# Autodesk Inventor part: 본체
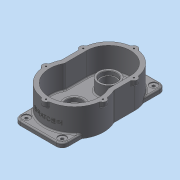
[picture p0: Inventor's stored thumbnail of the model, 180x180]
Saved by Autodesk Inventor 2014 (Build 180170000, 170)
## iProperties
Created: 2025-09
Part Number: 본체
Material: 일반
Document SubType Name: Modeling
Designer: dg
Density: 1 g/cm^3
Appearance: 기본값
Author: dg
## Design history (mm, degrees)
sketch "스케치1"
  geometry: L1 (-60, 0)-(-60, -48.184); L2 (60, 0)-(60, -48.184); A1 r 60 centre (0, 0) between (60, 0) and (-60, 0); A2 r 67 centre (0, -78) between (-60, -48.184) and (60, -48.184); 1 further point
  constraints: 4 end point, 4 point on circle, 2 centre point, 2 tangent, 1 coincident, 1 parallel, 1 vertical, 1 vertical alignment
  dimensions: "d0" = 120 diameter of A1; "d2" = 78 distance of point (0, 0) A2.centre; "d3" = 67 radius of A2
extrude "돌출1" new body sketch "스케치1" distance "d4" = 64; taper "d5" = 0 deg
feature "쉘1" dims "d6" = 10
sketch "스케치2"
  geometry: L1 (-55, 76)-(55, 76); L2 (55, 76)-(55, -161); L3 (55, -161)-(-55, -161); L4 (-55, -161)-(-55, 76); A1 r 60 centre (0, 0) between (60, 0) and (-60, 0) reference; 1 further point
  constraints: 8 end point, 2 parallel, 1 horizontal, 1 midpoint, 1 perpendicular, 1 vertical alignment
  dimensions: "d7" = 110 distance of L2.end L3.end; "d8" = 76 distance from line of L1 A1.centre; "d9" = 237 distance between parallel lines of L3 L1
extrude "돌출2" join sketch "스케치2" distance "d10" = 10; taper "d11" = 0 deg
sketch "스케치3"
  geometry: C1 r 23.5 at (0, 78); C2 r 23.5 at (0, 0); A1 r 57 centre (0, 0) between (-50, 27.368) and (50, 27.368) reference; A2 r 50 centre (0, 78) between (50, 78) and (-50, 78) reference
  constraints: 2 centre point, 2 coincident
  dimensions: "d12" = 47 diameter of C1; "d13" = 47 diameter of C2
extrude "돌출3" join sketch "스케치3" distance "d14" = 26; taper "d15" = 0 deg
extrude "돌출4" join sketch "스케치3" distance "d16" = 12; taper "d17" = 0 deg
hole "구멍1" diameter "d20" = 32; stored, may be unused: countersink angle "d24" = 90 deg, drill point angle "d26" = 0 deg; dims "d21" = 6, "d22" = 37, "d23" = 9, "d25" = 16, "d27" = 10, "d28" = 10
hole "구멍2" diameter "d31" = 30; stored, may be unused: countersink angle "d35" = 90 deg, drill point angle "d37" = 118 deg; dims "d29" = 10, "d30" = 10, "d32" = 6, "d33" = 37, "d34" = 9, "d36" = 16
hole "구멍3" diameter "d40" = 35; stored, may be unused: countersink angle "d44" = 90 deg, drill point angle "d46" = 0 deg; dims "d41" = 6, "d42" = 4, "d43" = 2, "d45" = 8.3, "d58" = 10, "d59" = 10
hole "구멍4" diameter "d49" = 28; stored, may be unused: countersink angle "d53" = 90 deg, drill point angle "d55" = 0 deg; dims "d50" = 6, "d51" = 4, "d52" = 2, "d54" = 3, "d56" = 10, "d57" = 10
fillet "모깎기1" dims "d72" = 14, "d73" = 0.3, "d74" = 13
sketch "스케치8"
  geometry: L1 (-60, 0)-(-60, -48.184) reference; L2 (60, -48.184)-(60, 0) reference; L3 (58, 0)-(58, -48.657); L4 (-58, -48.657)-(-58, 0); C1 r 8 at (58, 0); C2 r 8 at (-65, -78); C3 r 8 at (0, 58); C4 r 8 at (-58, 0); C5 r 8 at (0, -143); C6 r 8 at (65, -78); A1 r 50 centre (0, 0) between (50, 0) and (-50, 0) reference; A2 r 57 centre (0, -78) between (-51.3, -53.154) and (51.3, -53.154) reference; A3 r 60 centre (0, 0) between (60, 0) and (-60, 0) reference; A4 r 67 centre (0, -78) between (-60, -48.184) and (60, -48.184) reference; A5 r 58 centre (0, 0) between (58, 0) and (-58, 0); A6 r 65 centre (0, -78) between (-58, -48.657) and (58, -48.657)
  constraints: 8 centre point, 5 point on circle, 4 end point, 1 coincident, 1 horizontal alignment, 13 other
  dimensions: "d101" = 2 radial gap between concentric circles of A3 A5; "d102" = 16 diameter of C1; "d103" = 16 diameter of C2; "d106" = 180 deg dimension on A1.centre C1.centre C4.centre; "d110" = 180 deg dimension on A2.centre C2.centre C6.centre
extrude "돌출6" join sketch "스케치8" distance "d112" = 12; taper "d113" = 0 deg
fillet "모깎기2" dims "d75" = 3
fillet "모깎기3" dims "d76" = 3
fillet "모깎기4" dims "d77" = 3
sketch "스케치5"
  geometry: L1 (-41, 73)-(41, 73) reference; L2 (52, 62)-(52, 35.567) reference; L3 (-52, 35.567)-(-52, 62) reference; A1 r 11 centre (-41, -147) between (-52, -147) and (-41, -158) reference; A2 r 11 centre (41, -147) between (41, -158) and (52, -147) reference; A3 r 11 centre (41, 62) between (52, 62) and (41, 73) reference; A4 r 11 centre (-41, 62) between (-41, 73) and (-52, 62) reference; A5 r 63 centre (0, 0) between (52, 35.567) and (-52, 35.567) reference; 1 further point
hole "구멍5" sketch "스케치5" at (-41, -147), (41, -147), (41, 62), (-41, 62) diameter "d78" = 6.6; stored, may be unused: countersink angle "d82" = 90 deg, drill point angle "d84" = 118 deg; dims "d79" = 6, "d80" = 18, "d81" = 2, "d83" = 3
chamfer "모따기1" distance "d92" = 0.8; stored, may be unused: second distance "d93" = 2, angle "d94" = 30 deg
chamfer "모따기2" distance "d95" = 1; stored, may be unused: second distance "d96" = 2, angle "d97" = 30 deg
node "작업 평면1"
sketch "스케치7"
  geometry: L1 (55.514, 0)-(-55.514, 0) reference; 3 further points
  constraints: 1 vertical alignment, 1 other
  dimensions: "d98" = 30 distance from line of L1 point (0, 30)
feature "엠보싱1" sketch "스케치7" dims "d0" = 120, "d2" = 78, "d3" = 67, "d99" = 0.5, "d100" = 0
sketch "스케치9"
  geometry: A1 r 8 centre (58, 0) between (60, -7.746) and (59.483, 7.861) reference; A2 r 8 centre (0, 58) between (7.861, 59.483) and (-7.861, 59.483) reference; A3 r 8 centre (-58, 0) between (-59.483, 7.861) and (-60, -7.746) reference; A4 r 8 centre (-65, -78) between (-66.538, -70.149) and (-66.538, -85.851) reference; A5 r 8 centre (0, -143) between (-7.851, -144.538) and (7.851, -144.538) reference; A6 r 8 centre (65, -78) between (66.538, -85.851) and (66.538, -70.149) reference
hole "구멍7" sketch "스케치9" at (0, 58), (-58, 0), (-65, -78), (0, -143), (65, -78), (58, 0) diameter "d114" = 3.242; stored, may be unused: countersink angle "d118" = 90 deg, drill point angle "d120" = 118 deg; dims "d115" = 8, "d116" = 4, "d117" = 2, "d119" = 10
fillet "모깎기5" dims "d121" = 3
node "솔리드1"
node "투영된 루프1"
